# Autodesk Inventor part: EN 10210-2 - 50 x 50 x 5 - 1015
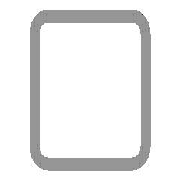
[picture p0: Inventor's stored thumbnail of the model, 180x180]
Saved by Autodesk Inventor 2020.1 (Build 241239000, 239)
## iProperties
_CCFamilyMember: 16
_CCFamilyDisplayName: DIN EN 10210-2 (USAS B17.1 quadratisch) - Rohrleitung — In Klammern angegebene Größen wurden aufgehoben
_FrameMemberDoc: Frame Member File
_Version: 15.0.0
_GetPNFromCC: 1
IsCustomPart: 1
Created: 2019-01
Part Number: EN 10210-2 - 50 x 50 x 5 - 1015
Material: Stahl, weich
Description: Rohrleitung
Document SubType Name: Modeling
Standard: DIN
Designer: lutzd
Standard Revision: 2006-07
Standards Organization: DIN
Language: de-DE
Size Designation: 50 x 50 x 5
Categories: <MemberInstance><Categories><Category DisplayName="Profile" InternalName="089c4875-fa83-4c05-b084-43b9cc11f5ed" Mnemonic="GRDR"><CategoryParameter DisplayName="
Stock Number: 50 x 50 x 5
Mass: 6957.24 g
Surface Area: 3453.64 cm^2
Volume: 886.272 cm^3
Density: 7.85 g/cm^3
Appearance: Halbpoliert
G_L: 1015,000 mm
G_W: 50,000 mm
G_H: 50,000 mm
Dimensions: 50x50x1015 mm
Mass: 6,957 kg
DocNumber: ADSK-014104
Folder: .
Title: Profil-Bauteil
Author: lutzd
Revision Number: -
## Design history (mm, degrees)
node "Startebene"
node "Endebene"
sketch "Skizze"
  geometry: L1 (-25, -17.5)-(-25, 17.5); L2 (-17.5, 25)-(17.5, 25); L3 (25, 17.5)-(25, -17.5); L4 (17.5, -25)-(-17.5, -25); L5 (-15, 20)-(15, 20); L6 (20, 15)-(20, -15); L7 (15, -20)-(-15, -20); L8 (-20, -15)-(-20, 15); L9 (0, 37.175)-(0, -37.175) reference; L10 (-37.175, 0)-(37.175, 0) reference; A1 r 7.5 centre (-17.5, -17.5) between (-25, -17.5) and (-17.5, -25); A2 r 7.5 centre (-17.5, 17.5) between (-17.5, 25) and (-25, 17.5); A3 r 7.5 centre (17.5, 17.5) between (25, 17.5) and (17.5, 25); A4 r 7.5 centre (17.5, -17.5) between (17.5, -25) and (25, -17.5); A5 r 5 centre (-15, -15) between (-20, -15) and (-15, -20); A6 r 5 centre (-15, 15) between (-15, 20) and (-20, 15); A7 r 5 centre (15, 15) between (20, 15) and (15, 20); A8 r 5 centre (15, -15) between (15, -20) and (20, -15)
  constraints: 16 end point, 16 point on circle, 16 tangent, 8 centre point, 6 equal radius, 4 parallel, 2 perpendicular, 2 other
  dimensions: "d7" = 7.5 radius of A1 (= G_IR); "d10" = 50 distance between parallel lines of L2 L4 (= G_H); "d11" = 50 distance between parallel lines of L1 L3 (= G_W); "d12" = 5 distance between parallel lines of L3 L6 (= G_T); "d15" = 25 distance between parallel lines of L2 L10 (= 0.5 x d10); "d16" = 25 distance between parallel lines of L9 L3 (= 0.5 x d11); "d19" = 5 radius of A5 (= G_T); "d20" = 5 distance between parallel lines of L4 L7 (= G_T)
extrude "Körper" new body sketch "Skizze" stored distance "d3" = 1015 (= G_L); taper "d4" = 0 deg
node "Driven Length"
  sketch "Sketch3"
    geometry: L1 (0, 0)-(10, 0) reference
    constraints: 2 end point, 1 horizontal
  workplane "Work Plane3"
  sketch "Sketch4"
    geometry: L1 (-2, 35)-(12, 35) reference; L2 (-2, 1050)-(12, 1050) reference
    dimensions: "d18" = 1015 distance between parallel lines of L1 L2 (derived)
body "Solid1"
other parameters: "G_W" = 50 [user parameter; used in 1 equation term], "G_H" = 50 [user parameter; used in 1 equation term], "G_T" = 5 [user parameter; used in 3 equation terms], "G_IR" = 7.5 [user parameter; used in 1 equation term], "G_L" = 1015 (= d18) [user parameter; used in 1 equation term], "G_OFFSET_START" = -35 [user parameter; used in 1 equation term], "G_OFFSET_END" = 0 [user parameter; used in 1 equation term], "d13" = 35 (= -G_OFFSET_START), "d17" = 90 deg
